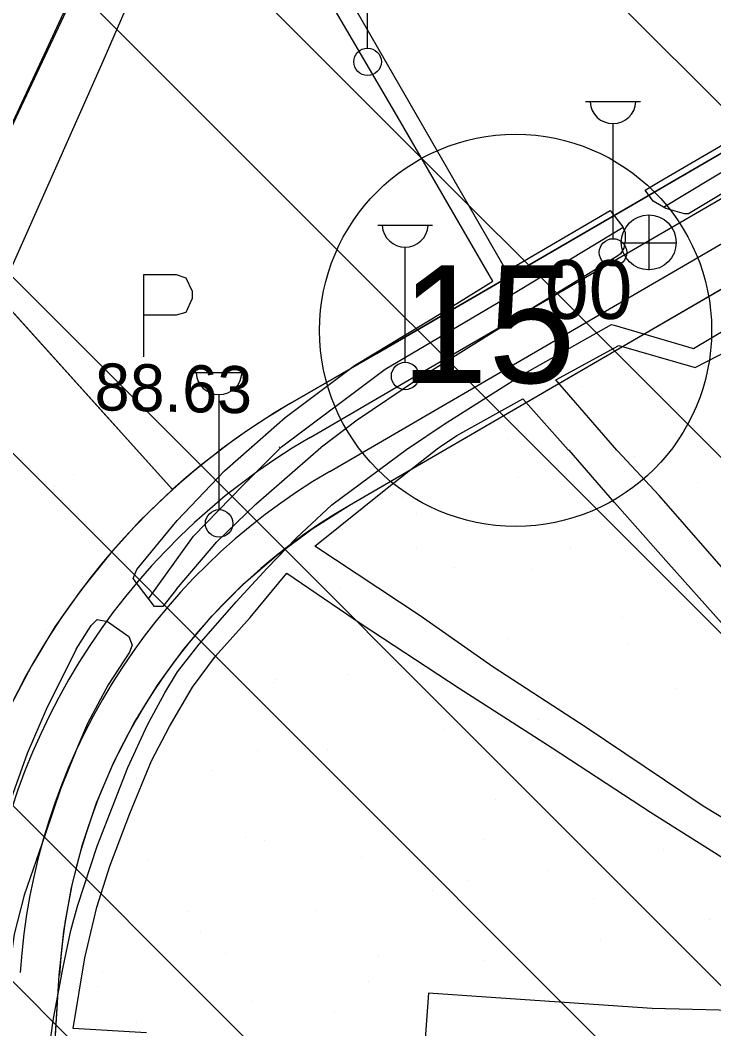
# Model space of a CAD drawing. Extents: x 417995 to 421451, y 4454518 to 4458015.
# Drawn here: x 420558.9 to 420647.4, y 4455736 to 4455864.6 of the extents above; entities that cross this region are included whole.
import ezdxf

# ---------------------------------------------------------------- set-up
doc = ezdxf.new("R2010")
doc.units = 0
for name, color, linetype in [('ADAKENARI', 7, 'Continuous'), ('KALDIRIM_FAT', 7, 'Continuous'), ('KD_DAIRE', 7, 'Continuous'), ('KD_YGEN', 7, 'Continuous'), ('PL_AYA_FUAR', 7, 'Continuous'), ('PL_AYA_PARK_DINLENME', 7, 'Continuous'), ('PL_KAMU_HİZMET_ALANI', 7, 'Continuous'), ('PL_TA_K_OTOPARK', 7, 'Continuous'), ('S_Cad_Sok_Lambasi', 7, 'Continuous'), ('S_Otopark', 7, 'Continuous'), ('S_Rogar_Kapagi', 7, 'Continuous'), ('Sinir_Tel_bir_taraf', 7, 'Continuous'), ('SN_TR_SIVILASMA', 7, 'Continuous'), ('TRFAT_PARKALANI', 7, 'Continuous'), ('Y_Yol_Kotu', 7, 'Continuous'), ('Yol_Kaldirim_kenari_bordurtasi', 7, 'Continuous'), ('Yol_Sose', 7, 'Continuous')]:
    doc.layers.add(name, color=color, linetype=linetype)

msp = doc.modelspace()

# ---------------------------------------------------------------- linework, layer by layer
at = {"layer": 'ADAKENARI'}
for p, q in [((420550.56, 4455835.6), (420578.04, 4455894.75)), ((420604.42, 4455822.11), (420705.46, 4455880.83)), ((420636.29, 4455823.29), (420701.58, 4455861.23)), ((420550.56, 4455835.6), (420578.39, 4455804.76)), ((420600.93, 4455802.74), (420636.29, 4455823.29)), ((420593.39, 4455815.7), (420604.42, 4455822.11)), ((420561.03, 4455696.59), (420563.93, 4455742.84))]:
    msp.add_line(p, q, dxfattribs=at)
for radius, start, end in [(89.66, 120.1641, 132.0545), (89.66, 132.0545, 176.4189), (74.66, 120.1641, 176.4189)]:
    msp.add_arc((420638.45, 4455738.18), radius, start, end, dxfattribs=at)
at = {"layer": 'KALDIRIM_FAT'}
for p, q in [((420608.38, 4455818.63), (420728.5, 4455888.44)), ((420612.88, 4455815.46), (420730.07, 4455883.57)), ((420595.91, 4455811.38), (420608.38, 4455818.63)), ((420598.42, 4455807.06), (420612.88, 4455815.46))]:
    msp.add_line(p, q, dxfattribs=at)
for radius in [84.66, 79.66]:
    msp.add_arc((420638.45, 4455738.18), radius, 120.1641, 176.4189, dxfattribs=at)
at = {"layer": 'KD_DAIRE'}
msp.add_circle((420622.14, 4455825.04), 25, dxfattribs=at)
at = {"layer": 'PL_AYA_FUAR'}
msp.add_lwpolyline([(420545.42, 4455447.04), (420563.93, 4455742.84), (420564.49, 4455748.45), (420565.48, 4455754), (420566.88, 4455759.47), (420568.69, 4455764.8), (420570.9, 4455769.99), (420573.49, 4455775), (420576.46, 4455779.79), (420579.77, 4455784.35), (420583.42, 4455788.65), (420587.39, 4455792.66), (420591.64, 4455796.35), (420596.17, 4455799.72), (420600.93, 4455802.74), (420701.58, 4455861.23), (420708.62, 4455863.92), (420715.79, 4455864.57), (420723.78, 4455862.78), (420730.13, 4455859.19), (420735, 4455853.4), (420771.9, 4455797.51), (420787.06, 4455778.4), (420884.04, 4455668.02)], dxfattribs=at)
at = {"layer": 'PL_AYA_PARK_DINLENME'}
msp.add_lwpolyline([(420516.32, 4455752.85), (420525.22, 4455781.05), (420550.56, 4455835.6), (420578.39, 4455804.76), (420574.22, 4455800.75), (420570.32, 4455796.47), (420566.7, 4455791.96), (420563.38, 4455787.22), (420560.38, 4455782.28), (420557.7, 4455777.15), (420555.35, 4455771.87), (420553.35, 4455766.44), (420551.71, 4455760.89), (420550.42, 4455755.25), (420549.51, 4455749.54), (420548.96, 4455743.78), (420548.08, 4455729.82), (420544.57, 4455671.28), (420495.57, 4455677.66), (420499.28, 4455692.79), (420506.44, 4455709.38), (420511.56, 4455731.89)], close=True, dxfattribs=at)
at = {"layer": 'PL_KAMU_HİZMET_ALANI'}
msp.add_lwpolyline([(420584.65, 4456067.45), (420582.08, 4456000.28), (420578.04, 4455894.75), (420575.94, 4455889.49), (420550.56, 4455835.6), (420525.22, 4455781.05), (420516.32, 4455752.85), (420511.56, 4455731.89), (420506.44, 4455709.38), (420499.28, 4455692.79), (420495.57, 4455677.66), (420488.85, 4455650.29), (420482.66, 4455589.65), (420479.31, 4455554.16), (420467.35, 4455501.65), (420461.1, 4455474.22), (420459.55, 4455467.41), (420458.85, 4455454.77), (420457.92, 4455437.99), (420419.68, 4455375.72)], dxfattribs=at)
at = {"layer": 'PL_TA_K_OTOPARK'}
msp.add_lwpolyline([(420578.04, 4455894.75), (420621.81, 4455921.26), (420693.23, 4455965.73), (420713.63, 4455902.08), (420714.27, 4455899.43), (420714.5, 4455896.71), (420714.32, 4455893.98), (420713.73, 4455891.31), (420712.75, 4455888.76), (420711.4, 4455886.39), (420709.7, 4455884.25), (420707.71, 4455882.38), (420705.46, 4455880.83), (420604.42, 4455822.11), (420593.39, 4455815.7), (420591.4, 4455814.51), (420589.43, 4455813.26), (420587.5, 4455811.97), (420585.61, 4455810.62), (420583.75, 4455809.23), (420581.92, 4455807.78), (420580.13, 4455806.29), (420578.39, 4455804.76), (420550.56, 4455835.6)], close=True, dxfattribs=at)
at = {"layer": 'S_Cad_Sok_Lambasi'}
for p, q in [((420603.26, 4455861.03), (420603.26, 4455875.7)), ((420631.06, 4455854.23), (420638.06, 4455854.23)), ((420634.56, 4455836.73), (420634.56, 4455851.41)), ((420604.54, 4455838.47), (420611.54, 4455838.47)), ((420608.04, 4455820.97), (420608.04, 4455835.64)), ((420580.81, 4455819.68), (420587.81, 4455819.68)), ((420584.31, 4455802.18), (420584.31, 4455816.85))]:
    msp.add_line(p, q, dxfattribs=at)
for centre in [(420603.26, 4455859.28), (420634.56, 4455834.98), (420608.04, 4455819.22), (420584.31, 4455800.43)]:
    msp.add_circle(centre, 1.75, dxfattribs=at)
for centre in [(420634.56, 4455854.33), (420608.04, 4455838.57), (420584.31, 4455819.78)]:
    msp.add_arc(centre, 2.93, 183.298, 356.9072, dxfattribs=at)
at = {"layer": 'S_Otopark'}
for points in [[(420574.73, 4455832.16), (420578.82, 4455832.16)], [(420574.73, 4455821.66), (420574.73, 4455832.16)], [(420578.82, 4455832.16), (420580.05, 4455831.74), (420580.89, 4455830.03), (420580.89, 4455829.12), (420580.05, 4455827.33), (420578.82, 4455826.98)], [(420578.82, 4455826.98), (420574.73, 4455826.98)]]:
    msp.add_lwpolyline(points, dxfattribs=at)
at = {"layer": 'S_Rogar_Kapagi'}
for p, q in [((420639.17, 4455832.73), (420639.17, 4455839.73)), ((420635.6, 4455836.19), (420642.6, 4455836.19))]:
    msp.add_line(p, q, dxfattribs=at)
msp.add_circle((420639.12, 4455836.26), 3.5, dxfattribs=at)
at = {"layer": 'Sinir_Tel_bir_taraf'}
msp.add_lwpolyline([(420588.51, 4455810.25), (420588.43, 4455810.18)], dxfattribs=at)
at = {"layer": 'SN_TR_SIVILASMA'}
for p, q in [((421268.85, 4455233.21), (420151.38, 4456350.68)), ((421268.38, 4455188.77), (420123.47, 4456333.68)), ((421268.15, 4455166.56), (420116.87, 4456317.84)), ((421267.69, 4455122.12), (420103.66, 4456286.14)), ((421267.46, 4455099.9), (420097.06, 4456270.29)), ((421266.99, 4455055.46), (420083.86, 4456238.6)), ((421266.76, 4455033.24), (420079.94, 4456220.06))]:
    msp.add_line(p, q, dxfattribs=at)
at = {"layer": 'TRFAT_PARKALANI'}
for p, q in [((420645.4, 4455820.52), (420645.4, 4455820.52)), ((420630.62, 4455817.92), (420630.62, 4455817.92)), ((420621.04, 4455811.3), (420621.04, 4455811.3)), ((420642.47, 4455811.66), (420642.47, 4455811.66)), ((420637.29, 4455808.94), (420637.29, 4455808.94)), ((420565.72, 4455806.65), (420565.72, 4455806.65)), ((420622.51, 4455806.33), (420622.51, 4455806.33)), ((420563.36, 4455805.09), (420563.36, 4455805.09)), ((420645.38, 4455805.62), (420645.38, 4455805.62)), ((420607.74, 4455803.73), (420607.74, 4455803.73)), ((420609.54, 4455801.65), (420609.54, 4455801.65)), ((420643.95, 4455799.96), (420643.95, 4455799.96)), ((420609.46, 4455797.17), (420609.46, 4455797.17)), ((420629.17, 4455797.35), (420629.17, 4455797.35)), ((420570.02, 4455796.11), (420570.02, 4455796.11)), ((420639.87, 4455796.89), (420639.87, 4455796.89)), ((420614.4, 4455794.75), (420614.4, 4455794.75)), ((420624.23, 4455794.57), (420624.23, 4455794.57)), ((420566.92, 4455793.63), (420566.92, 4455793.63)), ((420599.63, 4455792.14), (420599.63, 4455792.14)), ((420584.86, 4455789.54), (420584.86, 4455789.54)), ((420635.83, 4455788.37), (420635.83, 4455788.37)), ((420562.25, 4455786.95), (420562.25, 4455786.95)), ((420621.06, 4455785.77), (420621.06, 4455785.77)), ((420636.49, 4455785.1), (420636.49, 4455785.1)), ((420606.29, 4455783.16), (420606.29, 4455783.16)), ((420606.85, 4455782.4), (420606.85, 4455782.4)), ((420591.52, 4455780.56), (420591.52, 4455780.56)), ((420600.65, 4455781.14), (420600.65, 4455781.14)), ((420591.21, 4455780.08), (420591.21, 4455780.08)), ((420642.49, 4455779.39), (420642.49, 4455779.39)), ((420576.75, 4455777.95), (420576.75, 4455777.95)), ((420627.72, 4455776.79), (420627.72, 4455776.79)), ((420625, 4455775.46), (420625, 4455775.46)), ((420612.95, 4455774.18), (420612.95, 4455774.18)), ((420620.76, 4455774.87), (420620.76, 4455774.87)), ((420589.16, 4455771.5), (420589.16, 4455771.5)), ((420598.18, 4455771.58), (420598.18, 4455771.58)), ((420635.53, 4455772.27), (420635.53, 4455772.27)), ((420583.41, 4455768.98), (420583.41, 4455768.98)), ((420573.84, 4455767.92), (420573.84, 4455767.92)), ((420634.38, 4455767.81), (420634.38, 4455767.81)), ((420619.61, 4455765.2), (420619.61, 4455765.2)), ((420604.84, 4455762.6), (420604.84, 4455762.6)), ((420587.74, 4455760.39), (420587.74, 4455760.39)), ((420590.07, 4455760), (420590.07, 4455760)), ((420618.15, 4455760.1), (420618.15, 4455760.1)), ((420641.04, 4455758.83), (420641.04, 4455758.83)), ((420575.29, 4455757.39), (420575.29, 4455757.39)), ((420602.51, 4455757.78), (420602.51, 4455757.78)), ((420626.27, 4455756.22), (420626.27, 4455756.22)), ((420616.11, 4455754.94), (420616.11, 4455754.94)), ((420611.5, 4455753.62), (420611.5, 4455753.62)), ((420632.06, 4455752.57), (420632.06, 4455752.57)), ((420580.27, 4455750.98), (420580.27, 4455750.98)), ((420596.73, 4455751.02), (420596.73, 4455751.02)), ((420646.83, 4455749.97), (420646.83, 4455749.97)), ((420581.95, 4455748.41), (420581.95, 4455748.41)), ((420640.45, 4455749.26), (420640.45, 4455749.26)), ((420632.93, 4455747.24), (420632.93, 4455747.24)), ((420567.18, 4455745.81), (420567.18, 4455745.81)), ((420585.13, 4455745.61), (420585.13, 4455745.61)), ((420604.61, 4455745.3), (420604.61, 4455745.3)), ((420618.16, 4455744.64), (420618.16, 4455744.64)), ((420569.49, 4455743.3), (420569.49, 4455743.3)), ((420603.39, 4455742.04), (420603.39, 4455742.04)), ((420568.78, 4455741.34), (420568.78, 4455741.34)), ((420588.62, 4455739.43), (420588.62, 4455739.43)), ((420599.04, 4455738.09), (420599.04, 4455738.09)), ((420629.45, 4455737.8), (420629.45, 4455737.8)), ((420639.59, 4455738.27), (420639.59, 4455738.27)), ((420573.84, 4455736.83), (420573.84, 4455736.83))]:
    msp.add_line(p, q, dxfattribs=at)
at = {"layer": 'Yol_Kaldirim_kenari_bordurtasi'}
for points in [[(420641.01, 4455840.76), (420677.83, 4455862.92), (420691.88, 4455871.22)], [(420592.25, 4455810.14), (420592.28, 4455810.17), (420605.51, 4455820.1), (420622.52, 4455830.13), (420635.84, 4455838.19)], [(420635.05, 4455809.78), (420627.28, 4455818.75), (420635.3, 4455823.1), (420645.03, 4455820.32), (420656.5, 4455826.2), (420664.45, 4455810.33)], [(420612.42, 4455810.15), (420614.65, 4455811.62), (420623.05, 4455816.3), (420628.86, 4455809.82)], [(420575.32, 4455790.83), (420581.04, 4455798.79), (420587.37, 4455805.3), (420592.25, 4455810.14)], [(420591.96, 4455810.14), (420592.04, 4455810.21)], [(420605.99, 4455805.15), (420612.13, 4455809.93)], [(420612.13, 4455809.93), (420612.42, 4455810.15)], [(420628.86, 4455809.82), (420628.92, 4455809.75)], [(420635.14, 4455809.69), (420635.05, 4455809.78)], [(420628.92, 4455809.75), (420634.72, 4455803.1)], [(420640.44, 4455803.97), (420635.14, 4455809.69)], [(420634.12, 4455803.8), (420641.62, 4455795.3), (420648.41, 4455787.74), (420657.85, 4455777.5), (420664.68, 4455769.91), (420660.46, 4455763.61), (420657.12, 4455757.68), (420646.08, 4455764.38), (420631.12, 4455774.41), (420619.24, 4455782.13), (420609.97, 4455788.64), (420596.53, 4455797.53), (420605.99, 4455805.15)], [(420668.53, 4455801.74), (420674.58, 4455790.12), (420678.54, 4455782.11), (420674.16, 4455778.83), (420667.93, 4455773.06), (420661.11, 4455780.96), (420650.45, 4455792.57), (420640.44, 4455803.97)], [(420575.04, 4455735.47), (420565.68, 4455736.02), (420567.19, 4455745.02), (420568.7, 4455751.51), (420570.38, 4455756.73), (420572.94, 4455763.44), (420575.68, 4455770.16), (420577.97, 4455774.55), (420580.92, 4455779.55), (420583.86, 4455783.48), (420588.27, 4455788.45), (420592.97, 4455794.07), (420602.45, 4455787.64), (420614.94, 4455779.42), (420626.8, 4455771.83), (420639.34, 4455763.61), (420655.33, 4455753.52), (420653.57, 4455748.07), (420652.34, 4455742.15), (420651.56, 4455738.28), (420639.55, 4455738.58), (420618.39, 4455740.03), (420611.03, 4455740.52), (420610.52, 4455733.57)]]:
    msp.add_lwpolyline(points, dxfattribs=at)
at = {"layer": 'Yol_Sose'}
for points in [[(420695.05, 4455876.18), (420713.1, 4455887.06), (420687.66, 4455930.97), (420677.4, 4455948.31), (420649.89, 4455932.39), (420613.33, 4455911.21), (420585.27, 4455894.31), (420599.67, 4455869.56), (420620.98, 4455832.6), (420634.21, 4455840.32)], [(420619.25, 4455831.32), (420606.69, 4455852.93), (420595.97, 4455871.26), (420583.83, 4455892.33), (420569.47, 4455859.34), (420555.83, 4455828.67), (420547.53, 4455810.61)], [(420640.57, 4455844.05), (420662.71, 4455856.98), (420665.23, 4455858.74), (420690.7, 4455873.74)], [(420691.94, 4455870.66), (420691.82, 4455869.63), (420691.69, 4455868.83), (420691.33, 4455868.05), (420690.91, 4455867.74), (420679.87, 4455861.28), (420644.2, 4455839.91), (420643.68, 4455839.89), (420641.3, 4455840.59), (420639.67, 4455841.52)], [(420634.71, 4455825.71), (420644.82, 4455822.73), (420669.58, 4455837.48), (420671.93, 4455848.48)], [(420639.67, 4455841.52), (420638.66, 4455842.93), (420640.57, 4455844.05)], [(420634.21, 4455840.32), (420635.81, 4455838.26), (420636.11, 4455837.51), (420636.11, 4455836.45), (420635.93, 4455835.51), (420635.53, 4455834.8), (420635.05, 4455834.44), (420621.02, 4455825.89), (420609.64, 4455818.78), (420601.93, 4455813.58), (420597.39, 4455810.15)], [(420588.5, 4455810.18), (420592.75, 4455813.92), (420601.57, 4455820.56), (420612.85, 4455827.36), (420619.25, 4455831.32)], [(420608.38, 4455809.97), (420608.47, 4455810.04), (420613.02, 4455813.1), (420622.99, 4455819.39), (420634.38, 4455825.78), (420634.71, 4455825.71)], [(420558.37, 4455683.41), (420559.37, 4455695.18), (420561.47, 4455725.17), (420563.18, 4455737.32), (420564.42, 4455743.86), (420565.4, 4455748.5), (420566.24, 4455751.64), (420568.75, 4455759.29), (420572.69, 4455769.31), (420575.17, 4455774.75), (420577.41, 4455778.84), (420579.02, 4455781.49), (420581.79, 4455785.05), (420586.5, 4455790.41), (420590.45, 4455794.72), (420594.17, 4455798.57), (420598.68, 4455802.8), (420608.38, 4455809.97)], [(420578.9, 4455792.04), (420577.13, 4455789.84), (420576.07, 4455789.85), (420573.36, 4455793.39), (420573.83, 4455794.56), (420578.96, 4455800.8), (420585.02, 4455807.11), (420588.5, 4455810.18)], [(420578.9, 4455792.04), (420584.04, 4455798.08), (420588.99, 4455802.9), (420597.3, 4455810.09)], [(420597.39, 4455810.15), (420597.3, 4455810.09)], [(420566.07, 4455784.38), (420567.98, 4455787.43), (420568.74, 4455788.19), (420570.09, 4455787.91), (420572.8, 4455785.99), (420573.23, 4455784.92), (420572.89, 4455783.99), (420570.15, 4455779.84)], [(420566.07, 4455784.38), (420562.25, 4455776.72), (420559.85, 4455771.09), (420557.37, 4455764.18), (420554.41, 4455754.98), (420552.77, 4455755.54)], [(420570.15, 4455779.84), (420567.52, 4455774.93), (420566.31, 4455772.03), (420564.08, 4455766.54), (420562.13, 4455760.77), (420559.46, 4455753.03), (420558.19, 4455748.06), (420556.01, 4455732.58), (420553.98, 4455714.34), (420551.99, 4455690.94), (420549.92, 4455668.91), (420549.2, 4455656.34), (420545.93, 4455656.45), (420545.16, 4455641.14), (420543.9, 4455618.83), (420542.03, 4455589.29), (420539.87, 4455560.44), (420538.86, 4455545.1)]]:
    msp.add_lwpolyline(points, dxfattribs=at)

# ---------------------------------------------------------------- texts
at = {"layer": 'KD_YGEN'}
for s, height, p in [('15', 15, (420607.48, 4455818.34)), ('00', 7.5, (420625.88, 4455826.5))]:
    msp.add_text(s, height=height, dxfattribs=at).set_placement(p)
at = {"layer": 'Y_Yol_Kotu'}
msp.add_text('88.63', height=6, rotation=358.8289, dxfattribs=at).set_placement((420568.4, 4455814.86))

doc.saveas('drawing.dxf')
